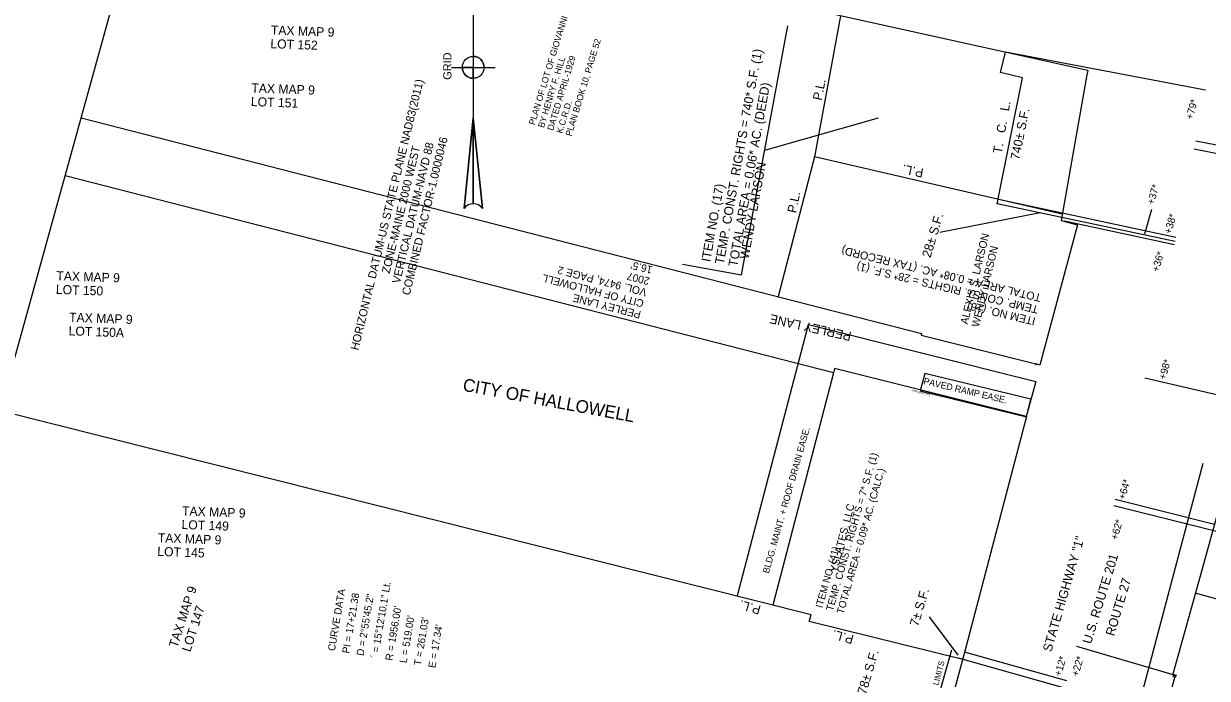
# Model space of a CAD drawing. Extents: x 1133267 to 1139526, y 528613 to 531538.
# Drawn here: x 1137049.2 to 1137374.5, y 529576.6 to 529756.7 of the extents above; entities that cross this region are included whole.
import ezdxf

# ---------------------------------------------------------------- set-up
doc = ezdxf.new("R2010")
doc.units = 0
for name, color, linetype in [('D_Roadway_Centerline_CurveData', 7, 'Continuous'), ('E_Property_Line', 7, 'Continuous'), ('E_Property_LotLine', 7, 'Continuous'), ('E_ROW_Line', 7, 'Continuous'), ('E_ROW_TieLine', 7, 'Continuous'), ('MISCELLN TEXT', 7, 'Continuous'), ('North Arrows', 7, 'Continuous'), ('P_Ease_Temp_Grading_Line', 7, 'Continuous'), ('P_ROW_Tie_Lines', 7, 'Continuous'), ('PROPERTY LINES', 7, 'Continuous'), ('PROPERTY NOTES', 7, 'Continuous'), ('PRP OWNER NAMES', 7, 'Continuous'), ('PRPTY SETUPS', 7, 'Continuous'), ('ROW REFERENCES', 7, 'Continuous'), ('TEMP RIGHTS', 7, 'Continuous'), ('Temp Rights Text', 7, 'Continuous'), ('TIE STATIONS', 7, 'Continuous')]:
    doc.layers.add(name, color=color, linetype=linetype)

msp = doc.modelspace()

# ---------------------------------------------------------------- linework, layer by layer
at = {"layer": 'E_Property_Line'}
for p, q in [((1137334.63, 529704.34), (1137266.52, 529720.11)), ((1137271.77, 529660.7), (1137255.05, 529596.8)), ((1137265.64, 529594.14), (1137039.69, 529650.92)), ((1137371.08, 529600.14), (1137505.47, 529563.04))]:
    msp.add_line(p, q, dxfattribs=at)
for points in [[(1137273.65, 529758.87), (1137266.52, 529720.11), (1137256.59, 529681.62)], [(1137307.27, 529581.87), (1137265.07, 529592.27), (1137265.65, 529594.18)]]:
    msp.add_lwpolyline(points, dxfattribs=at)
at = {"layer": 'E_Property_LotLine'}
msp.add_lwpolyline([(1137245.35, 529599.45), (1137264.87, 529673.92), (1137327.35, 529658.27), (1137324.75, 529648.61)], dxfattribs=at)
msp.add_lwpolyline([(1137295.62, 529655.68), (1137324.77, 529648.61), (1137326.01, 529653.46), (1137296.85, 529660.53)], close=True, dxfattribs=at)
at = {"layer": 'E_ROW_Line'}
for p, q in [((1137046.52, 529664.13), (1137086.27, 529807.81)), ((1137341.63, 529743.84), (1137259.93, 529761.9))]:
    msp.add_line(p, q, dxfattribs=at)
for points in [[(1137341.64, 529743.84), (1137341.42, 529742.66), (1137334.32, 529702.54), (1137338.79, 529701.36), (1137328.51, 529662.8), (1137327.34, 529663.11), (1137327.27, 529662.74)], [(1137064.96, 529730.79), (1137295.99, 529671.52), (1137295.87, 529670.99), (1137327.34, 529663.11), (1137327.34, 529663.08)], [(1137324.78, 529648.64), (1137272.06, 529661.82), (1137271.77, 529660.7), (1137060.56, 529714.88)], [(1137324.78, 529648.64), (1137307.77, 529583.73), (1137286.81, 529506.12)], [(1137380.61, 529633.99), (1137373.03, 529606.41), (1137365, 529577.77), (1137365.64, 529577.56), (1137342.79, 529491.93)]]:
    msp.add_lwpolyline(points, dxfattribs=at)
at = {"layer": 'E_ROW_TieLine'}
for p, q in [((1137246.5, 529687.66), (1137259.2, 529756.08)), ((1137230.25, 529690.53), (1137246.5, 529687.66)), ((1137365.29, 529577.77), (1137365.07, 529577)), ((1137365.94, 529577.62), (1137365.72, 529576.85))]:
    msp.add_line(p, q, dxfattribs=at)
at = {"layer": 'North Arrows'}
for p, q in [((1137172.75, 529782.19), (1137172.75, 529707.19)), ((1137166.75, 529744.69), (1137178.75, 529744.69)), ((1137170.25, 529705.84), (1137172.75, 529730.84)), ((1137172.75, 529730.84), (1137175.25, 529705.84))]:
    msp.add_line(p, q, dxfattribs=at)
for points in [[(1137172.75, 529747.69), (1137172.75, 529744.69), (1137175.75, 529744.69)], [(1137172.75, 529741.69), (1137172.75, 529744.69), (1137169.75, 529744.69)], [(1137172.75, 529707.19), (1137172.75, 529730.84), (1137170.25, 529705.84)], [(1137175.25, 529705.84), (1137172.75, 529730.84), (1137172.75, 529707.19)]]:
    msp.add_lwpolyline(points, dxfattribs=at)
msp.add_circle((1137172.75, 529744.69), 3, dxfattribs=at)
for centre, start, end in [((1137172.75, 529744.69), 0, 90), ((1137172.75, 529744.69), 180, 270), ((1137172.75, 529704.19), 33.5573, 146.4427), ((1137172.75, 529704.19), 90, 146.4427), ((1137172.75, 529704.19), 33.5573, 90)]:
    msp.add_arc(centre, 3, start, end, dxfattribs=at)
at = {"layer": 'P_Ease_Temp_Grading_Line'}
msp.add_line((1137289.67, 529533.18), (1137304.33, 529584.5), dxfattribs=at)
msp.add_lwpolyline([(1137316.75, 529707.18), (1137323.74, 529741.84), (1137317.67, 529743.31), (1137319, 529748.85)], dxfattribs=at)
at = {"layer": 'P_ROW_Tie_Lines'}
for p, q in [((1137374.03, 529738.39), (1137319, 529748.85)), ((1137252.85, 529721.87), (1137284.13, 529730.76)), ((1137371.34, 529724.5), (1137410.59, 529716.75)), ((1137370.9, 529722.24), (1137406.74, 529715.12)), ((1137365.9, 529697.92), (1137317.09, 529708.32)), ((1137301.02, 529699.34), (1137328.56, 529704.73)), ((1137365.66, 529696.76), (1137316.75, 529707.18)), ((1137359.16, 529705.59), (1137357.22, 529698.81)), ((1137365.47, 529695.91), (1137335.22, 529702.35)), ((1137357.31, 529659.29), (1137396.26, 529650.21)), ((1137348.78, 529624.18), (1137387.58, 529614.43)), ((1137349.23, 529625.96), (1137376.52, 529619.09)), ((1137338.57, 529585.47), (1137365.64, 529577.56)), ((1137335.36, 529573.93), (1137306.13, 529582.15)), ((1137335.92, 529575.92), (1137307.75, 529583.81))]:
    msp.add_line(p, q, dxfattribs=at)
msp.add_lwpolyline([(1137373.27, 529635.69), (1137335.05, 529491.51)], dxfattribs=at)
at = {"layer": 'Temp Rights Text'}
msp.add_line((1137298.02, 529593.56), (1137305.98, 529583.05), dxfattribs=at)

# ---------------------------------------------------------------- texts
at = {"layer": 'D_Roadway_Centerline_CurveData'}
for s, p in [('CURVE DATA', (1137134.71, 529584.06)), ('´ = 15%%d12\'10.1" Lt.', (1137146.54, 529582.06)), ('PI = 17+21.38', (1137138.65, 529583.39)), ('D = 2%%d55\'45.2"', (1137142.6, 529582.72)), ("R = 1956.00'", (1137150.49, 529581.39)), ("L = 519.00'", (1137154.43, 529580.73)), ("T = 261.03'", (1137158.37, 529580.06)), ("E = 17.34'", (1137162.32, 529579.39))]:
    msp.add_text(s, height=2, rotation=80.4136, dxfattribs=at).set_placement(p)
at = {"layer": 'MISCELLN TEXT'}
for s, height, rotation, p in [('PERLEY LANE', 2.5, 167.3726, (1137276.85, 529671.82)), ('PAVED RAMP EASE.', 1.8, 346.7328, (1137296.36, 529657.61)), ('2008 (9677-239)', 0.5, 345.7397, (1137293.34, 529655.6)), ('BLDG. MAINT. + ROOF DRAIN EASE.', 1.8, 74.2251, (1137253.98, 529605.37)), ('STATE HIGHWAY "1"', 2.5, 73.8085, (1137331.63, 529583.76)), ('U.S. ROUTE 201', 2.5, 72.9461, (1137342.55, 529585.92)), ('ROUTE 27', 2.5, 73.3576, (1137348.89, 529588.12))]:
    msp.add_text(s, height=height, rotation=rotation, dxfattribs=at).set_placement(p)
at = {"layer": 'North Arrows'}
for s, height, rotation, p in [('GRID', 2.249, 90, (1137166.75, 529741.26)), ('HORIZONTAL DATUM-US STATE PLANE NAD83(2011)', 2.2488, 76.4118, (1137141.15, 529666.73)), ('VERTICAL DATUM-NAVD 88', 2.2488, 76.4118, (1137152.57, 529685.08)), ('COMBINED FACTOR-1.0000046', 2.2488, 76.4118, (1137155.28, 529681.84)), ('ZONE-MAINE 2000 WEST', 2.2488, 76.4118, (1137149.74, 529687.83))]:
    msp.add_text(s, height=height, rotation=rotation, dxfattribs=at).set_placement(p)
at = {"layer": 'PROPERTY LINES'}
for rotation, p in [(78.3631, (1137268.47, 529735.45)), (168.3631, (1137296.67, 529716.78)), (78.3631, (1137261.47, 529704.47)), (163.7824, (1137251.97, 529596.52)), (164.7862, (1137277.51, 529588.44))]:
    msp.add_text('P.L.', height=2.49, rotation=rotation, dxfattribs=at).set_placement(p)
at = {"layer": 'PROPERTY NOTES'}
for s, height, rotation, p in [('PLAN OF LOT OF GIOVANNI CIPRIANO', 1.75, 73.0445, (1137189.63, 529728.69)), ('TAX MAP 9', 2.5, 357.9281, (1137117.09, 529753.72)), ('LOT 152', 2.5, 357.9281, (1137116.95, 529749.97)), ('PLAN BOOK 10, PAGE 52', 1.75, 73.0445, (1137199.74, 529725.61)), ('BY HENRY F. HILL', 1.75, 73.0445, (1137192.16, 529727.92)), ('DATED APRIL-1929', 1.75, 73.0445, (1137194.69, 529727.15)), ('TAX MAP 9', 2.5, 357.9281, (1137111.72, 529737.8)), ('LOT 151', 2.5, 357.9281, (1137111.59, 529734.05)), ('K.C.R.D.', 1.75, 73.0445, (1137197.21, 529726.38)), ('TAX MAP 9', 2.5, 357.9281, (1137058.12, 529686.15)), ('LOT 150', 2.5, 357.9281, (1137057.99, 529682.4)), ('TAX MAP 9', 2.5, 357.9281, (1137061.63, 529674.73)), ('LOT 150A', 2.5, 357.9281, (1137061.49, 529670.99)), ('TAX MAP 9', 2.5, 357.9281, (1137092.67, 529621.47)), ('LOT 149', 2.5, 357.9281, (1137092.53, 529617.72)), ('TAX MAP 9', 2.5, 357.9281, (1137086.01, 529614.08)), ('LOT 145', 2.5, 357.9281, (1137085.87, 529610.34)), ('TAX MAP 9', 2.5, 71.9723, (1137091.39, 529584.9)), ('LOT 147', 2.5, 71.9723, (1137094.96, 529583.74))]:
    msp.add_text(s, height=height, rotation=rotation, dxfattribs=at).set_placement(p)
at = {"layer": 'PRP OWNER NAMES'}
for s, height, rotation, p in [('WENDY LARSON', 2.49, 79.6855, (1137248.4, 529691.82)), ('ALEXIS S. LARSON', 2.1, 76.535, (1137308.64, 529673.87)), ('WENDY LARSON', 2.1, 76.535, (1137311.73, 529673.13)), ('CITY OF HALLOWELL', 3.5, 349.4782, (1137169.67, 529655.77)), ('YSLATES, LLC', 2.1, 75.4951, (1137272.72, 529605.63))]:
    msp.add_text(s, height=height, rotation=rotation, dxfattribs=at).set_placement(p)
at = {"layer": 'PRPTY SETUPS'}
for s, height, rotation, p in [('TEMP. CONST. RIGHTS = 740* S.F. (1)', 2.5, 79.8214, (1137241.59, 529690.38)), ('TOTAL AREA = 0.06* AC. (DEED)', 2.5, 79.8214, (1137245.3, 529689.71)), ('ITEM NO. (17)', 2.5, 79.8214, (1137237.87, 529691.05)), ('TOTAL AREA = 0.08* AC. (TAX RECORD)', 2.2, 166.4239, (1137329.01, 529682.28)), ('TEMP. CONST. RIGHTS = 28* S.F. (1)', 2.2, 166.4239, (1137328.23, 529679.05)), ('ITEM NO. (16)', 2.2, 166.4239, (1137327.45, 529675.82)), ('TEMP. CONST. RIGHTS = 7* S.F. (1)', 2, 74.0651, (1137271.58, 529595.01)), ('TOTAL AREA = 0.09* AC. (CALC.)', 2, 74.0651, (1137274.49, 529594.18)), ('ITEM NO. (41)', 2, 74.0651, (1137268.68, 529595.84))]:
    msp.add_text(s, height=height, rotation=rotation, dxfattribs=at).set_placement(p)
at = {"layer": 'ROW REFERENCES'}
for s, height, p in [('VOL. 9474, PAGE 2', 2.1008, (1137220.6, 529683.72)), ('2007', 2.101, (1137221.39, 529686.79)), ("16.5'", 2.101, (1137222.18, 529689.86)), ('CITY OF HALLOWELL', 2.1008, (1137219.81, 529680.65)), ('PERLEY LANE', 2.1008, (1137219.01, 529677.58))]:
    msp.add_text(s, height=height, rotation=165.5386, dxfattribs=at).set_placement(p)
at = {"layer": 'TEMP RIGHTS'}
for s, height, rotation, p in [('T.   C.   L.', 2.49, 80.4603, (1137318, 529720.83)), ('LIMITS', 1.59, 75.4344, (1137300.6, 529574.6))]:
    msp.add_text(s, height=height, rotation=rotation, dxfattribs=at).set_placement(p)
at = {"layer": 'Temp Rights Text'}
for s, rotation, p in [('740± S.F.', 78.5301, (1137322.8, 529719.12)), ('28± S.F.', 73.2515, (1137298.41, 529692.17)), ('7± S.F.', 73.2515, (1137295.03, 529590.78)), ('78± S.F.', 73.2515, (1137280.66, 529572.05))]:
    msp.add_text(s, height=2.49, rotation=rotation, dxfattribs=at).set_placement(p)
at = {"layer": 'TIE STATIONS'}
for s, p in [('+79*', (1137370.42, 529730.17)), ('+37*', (1137359.83, 529706.76)), ('+38*', (1137364.54, 529698.69)), ('+36*', (1137361.15, 529688.29)), ('+98*', (1137363.02, 529658.64)), ('+64*', (1137351.87, 529625.64)), ('+62*', (1137349.79, 529614.59)), ('+12*', (1137334.29, 529577.02)), ('+22*', (1137339.05, 529577.02))]:
    msp.add_text(s, height=2.01, rotation=74.2706, dxfattribs=at).set_placement(p)

doc.saveas('drawing.dxf')
